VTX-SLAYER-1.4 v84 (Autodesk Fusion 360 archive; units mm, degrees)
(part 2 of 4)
sketch "Skizze49" plane through (0, 0, 7) normal (0, 0, 1) x axis (-1, 0, 0)
  curve K1 (-34.4729, 47.5027) -> (-34.8613, 50.4161)
  line L1 (-32.7992, 19.5622) -> (-34.4732, 21.3854)
  line L2 (21.7601, 20.324) -> (21.0607, 19.5622)
  curve K2 (14.991, 38.4401) -> (21.2218, 28.4813)
  curve K3 (14.991, 41.5582) -> (21.2218, 51.5169)
  line L3 (21.0607, 60.4361) -> (21.7601, 59.6743)
  line L4 (-34.4732, 58.6128) -> (-32.7992, 60.4361)
  line L5 (-23.7522, 44.4991) -> (-30.319, 44.4991)
  line L6 (-30.319, 41.4991) -> (-23.7522, 41.4991)
  line L7 (-23.7522, 38.4991) -> (-30.319, 38.4991)
  line L8 (-30.319, 35.4991) -> (-23.7522, 35.4991)
  curve K4 (-21.4163, 20.9358) -> (-22.7131, 20.0338)
  curve K5 (-21.4163, 59.0625) -> (-22.7131, 59.9644)
  curve K6 (23.3399, 24.4614) -> (21.2218, 28.4813)
  curve K7 (21.2218, 51.5169) -> (23.3399, 55.5369)
  line L9 (-26.3392, 32.4991) -> (-30.319, 32.4991)
  line L10 (-30.319, 29.4991) -> (-26.3392, 29.4991)
  curve K8 (-34.4732, 21.3854) -> (-34.8613, 29.5821)
  curve K9 (-34.8613, 50.4161) -> (-34.4732, 58.6128)
  curve K10 (-34.2161, 44.4991) -> (-34.4729, 47.5027)
  curve K11 (-34.0692, 39.9991) -> (-34.0919, 41.4991)
  curve K12 (-34.0919, 38.4991) -> (-34.0692, 39.9991)
  curve K13 (-34.0919, 38.4991) -> (-34.2161, 35.4991)
  curve K14 (-34.4729, 32.4955) -> (-34.2161, 35.4991)
  line L11 (-26.3392, 50.4991) -> (-30.319, 50.4991)
  line L12 (-30.319, 47.4991) -> (-26.3392, 47.4991)
  curve K15 (-5.8693, 25.0204) -> (1.6863, 24.3869)
  curve K16 (-5.8693, 54.9778) -> (1.6863, 55.6114)
  curve K17 (-32.7992, 19.5622) -> (-25.5215, 18.3445)
  curve K18 (-22.7131, 20.0338) -> (-25.5215, 18.3445)
  curve K19 (-5.8693, 25.0204) -> (-13.4249, 24.3869)
  curve K20 (10.9746, 20.0338) -> (13.7829, 18.3445)
  curve K21 (13.7829, 18.3445) -> (21.0607, 19.5622)
  curve K22 (14.9178, 39.9991) -> (14.991, 38.4401)
  curve K23 (14.9178, 39.9991) -> (14.991, 41.5582)
  curve K24 (13.7829, 61.6537) -> (21.0607, 60.4361)
  curve K25 (10.9746, 59.9644) -> (13.7829, 61.6537)
  curve K26 (-5.8693, 54.9778) -> (-13.4249, 55.6114)
  curve K27 (-22.7131, 59.9644) -> (-25.5215, 61.6537)
  curve K28 (-32.7992, 60.4361) -> (-25.5215, 61.6537)
  curve K29 (-34.0919, 41.4991) -> (-34.2161, 44.4991)
  curve K30 (-21.2077, 21.0728) -> (-21.4163, 20.9358)
  curve K31 (-13.5094, 24.37) -> (-21.2077, 21.0728)
  curve K32 (-13.4249, 24.3869) -> (-13.5094, 24.37)
  curve K33 (1.6863, 24.3869) -> (1.7709, 24.37)
  curve K34 (9.4692, 21.0728) -> (1.7709, 24.37)
  curve K35 (9.4692, 21.0728) -> (9.6778, 20.9358)
  curve K36 (9.6778, 20.9358) -> (10.9746, 20.0338)
  curve K37 (9.6778, 59.0625) -> (10.9746, 59.9644)
  curve K38 (9.4692, 58.9255) -> (9.6778, 59.0625)
  curve K39 (1.7709, 55.6283) -> (9.4692, 58.9255)
  curve K40 (1.6863, 55.6114) -> (1.7709, 55.6283)
  curve K41 (-13.4249, 55.6114) -> (-13.5094, 55.6283)
  curve K42 (-21.2077, 58.9255) -> (-13.5094, 55.6283)
  curve K43 (-21.2077, 58.9255) -> (-21.4163, 59.0625)
  curve K44 (-34.4729, 32.4955) -> (-34.8613, 29.5821)
  circle C1 centre (4.1749, 29.9966) radius 1.05
  circle C2 centre (-15.8251, 49.9966) radius 1.05
  circle C3 centre (-15.8251, 29.9966) radius 1.05
  circle C4 centre (4.1749, 49.9966) radius 1.05
  circle C5 centre (18.1718, 23.4983) radius 2
  circle C6 centre (-29.8282, 23.4983) radius 2
  circle C7 centre (18.1718, 56.4983) radius 2
  circle C8 centre (-29.8282, 56.4983) radius 2
  circle C9 centre (-15.8251, 49.9966) radius 2.1
  circle C10 centre (-15.8251, 29.9966) radius 2.1
  circle C11 centre (4.1749, 29.9966) radius 2.1
  circle C12 centre (4.1749, 49.9966) radius 2.1
  circle C13 centre (-5.8313, 39.9999) radius 2.625
  circle C14 centre (-15.8251, 49.9966) radius 1.05
  circle C15 centre (-15.8251, 29.9966) radius 1.05
  circle C16 centre (4.1749, 49.9966) radius 1.05
  circle C17 centre (4.1749, 29.9966) radius 1.05
  circle C18 centre (-15.8282, 29.9983) radius 2.1
  circle C19 centre (-15.8282, 49.9983) radius 2.1
  circle C20 centre (4.1718, 29.9983) radius 2.1
  circle C21 centre (-5.8282, 39.9983) radius 3
  circle C22 centre (4.1718, 49.9983) radius 2.1
  arc A1 centre (-23.7522, 42.9991) radius 1.5 clockwise from (-23.7522, 44.4991) to (-23.7522, 41.4991)
  arc A2 centre (-30.319, 42.9991) radius 1.5 clockwise from (-30.319, 41.4991) to (-30.319, 44.4991)
  arc A3 centre (-30.319, 36.9991) radius 1.5 clockwise from (-30.319, 35.4991) to (-30.319, 38.4991)
  arc A4 centre (-23.7522, 36.9991) radius 1.5 clockwise from (-23.7522, 38.4991) to (-23.7522, 35.4991)
  arc A5 centre (17.3404, 24.3819) radius 6 clockwise from (23.3399, 24.4614) to (21.7601, 20.324)
  arc A6 centre (17.3404, 55.6164) radius 6 clockwise from (21.7601, 59.6743) to (23.3399, 55.5369)
  arc A7 centre (-26.3392, 30.9991) radius 1.5 clockwise from (-26.3392, 32.4991) to (-26.3392, 29.4991)
  arc A8 centre (-30.319, 30.9991) radius 1.5 clockwise from (-30.319, 29.4991) to (-30.319, 32.4991)
  arc A9 centre (-30.319, 48.9991) radius 1.5 clockwise from (-30.319, 47.4991) to (-30.319, 50.4991)
  arc A10 centre (-26.3392, 48.9991) radius 1.5 clockwise from (-26.3392, 50.4991) to (-26.3392, 47.4991)
  circle C23 centre (-29.8693, 56.4991) radius 2.55
  circle C24 centre (18.1307, 56.4991) radius 2.55
  circle C25 centre (-29.8693, 23.4991) radius 2.55
  circle C26 centre (18.1307, 23.4991) radius 2.55
  circle C27 centre (-5.8693, 39.9991) radius 2.55
  circle C28 centre (-15.8693, 49.9991) radius 1.05
  circle C29 centre (4.1307, 49.9991) radius 1.05
  circle C30 centre (-15.8693, 29.9991) radius 1.05
  circle C31 centre (4.1307, 29.9991) radius 1.05
  dimension "d443" diameter C5 = 4
  dimension "d444" diameter C6 = 4 (= "d443")
  dimension "d445" diameter C7 = 4 (= "d443")
  dimension "d446" diameter C8 = 4 (= "d443")
work_plane "WorkPlane5" AlongDistance 25
sketch "Skizze50" plane through (0, 0, 32) normal (0, 0, 1) x axis (-1, 0, 0)
  line L1 (-34.2161, 35.4991) -> (-33.5931, 35.4991)
  line L2 (-34.2172, 44.4991) -> (-33.5931, 44.4991)
  line L3 (-26.4943, 39.9991) -> (14.9178, 39.9991)
  line L4 (34.1307, 43.8641) -> (34.1307, 36.1341)
  line L5 (21.0607, 19.5622) -> (32.5504, 32.0762)
  line L6 (-32.7992, 19.5622) -> (-33.4986, 20.324)
  line L7 (32.5504, 32.0762) -> (21.0607, 19.5622)
  line L8 (34.1307, 43.8641) -> (34.1307, 36.1341)
  line L9 (21.0607, 60.4361) -> (32.5504, 47.922)
  line L10 (-33.4986, 59.6743) -> (-32.7992, 60.4361)
  curve K1 (-34.4729, 47.5027) -> (-34.8613, 50.4161)
  line L11 (-32.7992, 19.5622) -> (-34.4732, 21.3854)
  line L12 (21.7601, 20.324) -> (21.0607, 19.5622)
  line L13 (21.0607, 60.4361) -> (21.7601, 59.6743)
  line L14 (-34.4732, 58.6128) -> (-32.7992, 60.4361)
  curve K2 (9.6778, 20.9358) -> (10.9746, 20.0338)
  curve K3 (9.6778, 59.0625) -> (10.9746, 59.9644)
  curve K4 (-21.4163, 20.9358) -> (-22.7131, 20.0338)
  curve K5 (-21.4163, 59.0625) -> (-22.7131, 59.9644)
  curve K6 (-35.0785, 55.5369) -> (-32.9603, 51.5169)
  curve K7 (-32.9603, 28.4813) -> (-35.0785, 24.4614)
  curve K8 (23.3399, 24.4614) -> (21.2218, 28.4813)
  curve K9 (21.2218, 51.5169) -> (23.3399, 55.5369)
  line L15 (-26.3392, 32.4991) -> (-30.319, 32.4991)
  line L16 (-30.319, 29.4991) -> (-26.3392, 29.4991)
  curve K10 (-34.4732, 21.3854) -> (-34.8613, 29.5821)
  curve K11 (-34.8613, 50.4161) -> (-34.4732, 58.6128)
  curve K12 (-34.2161, 44.4991) -> (-34.4729, 47.5027)
  curve K13 (-34.0919, 41.4991) -> (-34.2161, 44.4991)
  curve K14 (-34.0692, 39.9991) -> (-34.0919, 41.4991)
  curve K15 (-34.0919, 38.4991) -> (-34.0692, 39.9991)
  curve K16 (-34.0919, 38.4991) -> (-34.2161, 35.4991)
  curve K17 (-34.4729, 32.4955) -> (-34.2161, 35.4991)
  line L17 (-26.3392, 50.4991) -> (-30.319, 50.4991)
  line L18 (-30.319, 47.4991) -> (-26.3392, 47.4991)
  curve K18 (-5.8693, 54.9778) -> (1.6863, 55.6114)
  curve K19 (-5.8693, 54.9778) -> (-13.4249, 55.6114)
  curve K20 (-5.8693, 25.0204) -> (-13.4249, 24.3869)
  curve K21 (-5.8693, 25.0204) -> (1.6863, 24.3869)
  curve K22 (-5.8693, 25.0204) -> (1.6863, 24.3869)
  curve K23 (-5.8693, 54.9778) -> (1.6863, 55.6114)
  curve K24 (-25.5215, 18.3445) -> (-32.7992, 19.5622)
  curve K25 (-22.7131, 20.0338) -> (-25.5215, 18.3445)
  curve K26 (10.9746, 20.0338) -> (13.7829, 18.3445)
  curve K27 (21.0607, 19.5622) -> (13.7829, 18.3445)
  curve K28 (21.0607, 60.4361) -> (13.7829, 61.6537)
  curve K29 (10.9746, 59.9644) -> (13.7829, 61.6537)
  curve K30 (-22.7131, 59.9644) -> (-25.5215, 61.6537)
  curve K31 (-25.5215, 61.6537) -> (-32.7992, 60.4361)
  curve K32 (-32.7992, 19.5622) -> (-25.5215, 18.3445)
  curve K33 (-22.7131, 20.0338) -> (-25.5215, 18.3445)
  curve K34 (-5.8693, 25.0204) -> (-13.4249, 24.3869)
  curve K35 (10.9746, 20.0338) -> (13.7829, 18.3445)
  curve K36 (13.7829, 18.3445) -> (21.0607, 19.5622)
  curve K37 (13.7829, 61.6537) -> (21.0607, 60.4361)
  curve K38 (10.9746, 59.9644) -> (13.7829, 61.6537)
  curve K39 (-5.8693, 54.9778) -> (-13.4249, 55.6114)
  curve K40 (-22.7131, 59.9644) -> (-25.5215, 61.6537)
  curve K41 (-32.7992, 60.4361) -> (-25.5215, 61.6537)
  curve K42 (-21.4163, 20.9358) -> (-22.7131, 20.0338)
  curve K43 (-13.5094, 24.37) -> (-21.4163, 20.9358)
  curve K44 (-13.4249, 24.3869) -> (-13.5094, 24.37)
  curve K45 (1.6863, 24.3869) -> (1.7709, 24.37)
  curve K46 (1.7709, 24.37) -> (9.6778, 20.9358)
  curve K47 (1.7709, 55.6283) -> (9.6778, 59.0625)
  curve K48 (1.6863, 55.6114) -> (1.7709, 55.6283)
  curve K49 (-13.4249, 55.6114) -> (-13.5094, 55.6283)
  curve K50 (-13.5094, 55.6283) -> (-21.4163, 59.0625)
  curve K51 (-21.4163, 59.0625) -> (-22.7131, 59.9644)
  curve K52 (-21.2077, 21.0728) -> (-21.4163, 20.9358)
  curve K53 (-13.5094, 24.37) -> (-21.2077, 21.0728)
  curve K54 (-13.4249, 24.3869) -> (-13.5094, 24.37)
  curve K55 (1.6863, 24.3869) -> (1.7709, 24.37)
  curve K56 (9.4692, 21.0728) -> (1.7709, 24.37)
  curve K57 (9.4692, 21.0728) -> (9.6778, 20.9358)
  curve K58 (9.6778, 20.9358) -> (10.9746, 20.0338)
  curve K59 (9.6778, 59.0625) -> (10.9746, 59.9644)
  curve K60 (9.4692, 58.9255) -> (9.6778, 59.0625)
  curve K61 (1.7709, 55.6283) -> (9.4692, 58.9255)
  curve K62 (1.6863, 55.6114) -> (1.7709, 55.6283)
  curve K63 (-13.4249, 55.6114) -> (-13.5094, 55.6283)
  curve K64 (-21.2077, 58.9255) -> (-13.5094, 55.6283)
  curve K65 (-21.2077, 58.9255) -> (-21.4163, 59.0625)
  curve K66 (-34.4729, 32.4955) -> (-34.8613, 29.5821)
  line L19 (3.2014, 37.2064) -> (18.1307, 23.4991)
  line L20 (3.2014, 42.7918) -> (18.1307, 56.4991)
  line L21 (25.9, 31.9611) -> (18.1307, 23.4991)
  line L22 (25.9, 48.0372) -> (18.1307, 56.4991)
  line L23 (6.5519, 27.8311) -> (12.5889, 23.7993)
  line L24 (6.5519, 52.1671) -> (12.5889, 56.1989)
  line L25 (-12.7701, 29.0204) -> (1.0316, 29.0204)
  line L26 (-12.7701, 50.9778) -> (1.0316, 50.9778)
  line L27 (19.9777, 28.7328) -> (21.5825, 30.4807)
  line L28 (19.9777, 51.2654) -> (21.5825, 49.5175)
  line L29 (-26.1937, 36.9643) -> (-19.1192, 29.9733)
  line L30 (-26.1937, 39.9991) -> (-26.1937, 36.9643)
  line L31 (-26.1937, 43.034) -> (-19.1192, 50.025)
  line L32 (-26.1937, 39.9991) -> (-26.1937, 43.034)
  line L33 (39.4861, -5.3562) -> (4.1307, 29.9991)
  line L34 (54.1307, 29.9991) -> (4.1307, 29.9991)
  line L35 (-51.2246, -5.3562) -> (-15.8693, 29.9991)
  line L36 (34.1307, 29.9991) -> (-15.8693, 29.9991)
  line L37 (-5.7883, 39.9991) -> (4.1307, 29.9991)
  line L38 (-5.7883, 39.9991) -> (-15.8693, 29.9991)
  line L39 (39.4861, 85.3545) -> (4.1307, 49.9991)
  line L40 (-5.7883, 39.9991) -> (4.1307, 49.9991)
  line L41 (-5.7883, 39.9991) -> (-15.8693, 49.9991)
  line L42 (-51.2246, 85.3545) -> (-15.8693, 49.9991)
  line L43 (-2.5295, 39.9991) -> (4.166, 33.2489)
  line L44 (0.9769, 30.784) -> (-5.7883, 37.6045)
  line L45 (-13.4558, 29.9991) -> (-5.7883, 37.6045)
  line L46 (-15.8592, 33.2491) -> (-9.0541, 39.9991)
  line L47 (0.9769, 49.2142) -> (-5.7883, 42.3937)
  line L48 (-2.5295, 39.9991) -> (4.166, 46.7493)
  line L49 (-13.4558, 49.9991) -> (-5.7883, 42.3937)
  line L50 (-15.8592, 46.7491) -> (-9.0541, 39.9991)
  line L51 (14.9457, 39.9991) -> (6.7725, 31.8921)
  line L52 (7.6315, 27.1101) -> (18.0788, 37.4728)
  line L53 (7.6315, 52.8881) -> (18.0788, 42.5254)
  line L54 (14.9457, 39.9991) -> (6.7725, 48.1061)
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  point P2 (-33.5931, 39.9991)
  point P7 (-26.4943, 39.9991)
  point P94 (-34.2161, 35.4991)
  point P141 (-34.2161, 35.4991)
  point P56 (18.1307, 23.4991)
  point P142 (18.1307, 23.4991)
  point P144 (18.1307, 56.4991)
  point P143 (3.2014, 37.2064)
  point P145 (3.2014, 42.7918)
  point P147 (18.1307, 56.4991)
  point P146 (25.9, 31.9611)
  point P148 (25.9, 48.0372)
  point P6 (14.9178, 39.9991)
  point P39 (31.849, 39.9991)
  point P150 (18.1307, 23.4991)
  point P156 (12.5889, 23.7993)
  point P158 (12.5889, 56.1989)
  point P157 (6.5519, 27.8311)
  point P159 (6.5519, 52.1671)
  point P160 (1.0316, 29.0204)
  point P162 (1.0316, 50.9778)
  point P161 (-12.7701, 29.0204)
  point P163 (-12.7701, 50.9778)
  point P164 (21.5825, 30.4807)
  point P166 (21.5825, 49.5175)
  point P165 (19.9777, 28.7328)
  point P167 (19.9777, 51.2654)
  point P170 (-26.1937, 39.9991)
  point P168 (-19.1192, 29.9733)
  point P171 (-19.1192, 50.025)
  point P169 (-26.1937, 36.9643)
  point P172 (-26.1937, 43.034)
  point P173 (-26.1937, 39.9991)
  point P106 (4.1307, 29.9991)
  point P174 (4.1307, 29.9991)
  point P72 (-15.8693, 29.9991)
  point P177 (-15.8693, 29.9991)
  point P180 (-5.7883, 39.9991)
  point P181 (-15.8693, 29.9991)
  point P182 (4.1307, 49.9991)
  point P175 (39.4861, -5.3562)
  point P183 (39.4861, 85.3545)
  point P186 (-15.8693, 49.9991)
  point P178 (-51.2246, -5.3562)
  point P187 (-51.2246, 85.3545)
  point P184 (-5.7883, 39.9991)
  point P185 (-15.8693, 49.9991)
  point P189 (-2.5295, 39.9991)
  point P190 (-5.7883, 37.6045)
  point P192 (-13.4558, 29.9991)
  point P193 (-9.0541, 39.9991)
  point P188 (4.166, 33.2489)
  point P197 (4.166, 46.7493)
  point P198 (-2.5295, 39.9991)
  point P195 (-5.7883, 42.3937)
  point P191 (0.9769, 30.784)
  point P196 (0.9769, 49.2142)
  point P199 (-13.4558, 49.9991)
  point P200 (-9.0541, 39.9991)
  point P194 (-15.8592, 33.2491)
  point P201 (-15.8592, 46.7491)
  point P203 (14.9457, 39.9991)
  point P205 (7.6315, 27.1101)
  point P202 (6.7725, 31.8921)
  point P208 (6.7725, 48.1061)
  point P209 (14.9457, 39.9991)
  point P204 (18.0788, 37.4728)
  point P206 (18.0788, 42.5254)
  point P207 (7.6315, 52.8881)
  point P128 (9.4692, 21.0728)
  point P74 (-5.8693, 25.0204)
  horizontal L1
  horizontal L2
  horizontal P2 P7
  coincident P94 P141
  coincident P56 P142
  symmetric L3 P142 P144
  symmetric L3 P143 P145
  perpendicular L19 L21
  parallel L5 L21
  symmetric L3 P142 P147
  symmetric L3 P146 P148
  horizontal P6 P39
  coincident P142 P150
  symmetric L3 P156 P158
  symmetric L3 P157 P159
  horizontal L25
  symmetric L3 P160 P162
  symmetric L3 P161 P163
  parallel L21 L27
  symmetric L3 P164 P166
  symmetric L3 P165 P167
  coincident L3 P170
  perpendicular L3 L30
  symmetric L3 P168 P171
  symmetric L3 P169 P172
  symmetric L3 P170 P173
  horizontal L34
  coincident P106 P174
  horizontal L36
  coincident P72 P177
  midpoint L3 P180
  coincident P72 P181
  symmetric L3 P174 P182
  symmetric L3 P175 P183
  symmetric L3 P177 P186
  symmetric L3 P178 P187
  symmetric L3 P180 P184
  symmetric L3 P181 P185
  coincident L3 P189
  parallel L37 L43
  parallel L37 L44
  vertical P180 P190
  coincident L36 P192
  perpendicular L44 L45
  coincident L3 P193
  parallel L45 L46
  symmetric L3 P188 P197
  symmetric L3 P189 P198
  symmetric L3 P190 P195
  symmetric L3 P191 P196
  symmetric L3 P192 P199
  symmetric L3 P193 P200
  symmetric L3 P194 P201
  coincident L3 P203
  coincident L23 P205
  parallel L51 L52
  perpendicular L37 L51
  symmetric L3 P202 P208
  symmetric L3 P203 P209
  symmetric L3 P204 P206
  symmetric L3 P205 P207
  dimension "d586" diameter = 9
  dimension "d636" diameter = 20
  dimension "d1095" distance = 4
  dimension "d1096" distance = 4
  dimension "d1098" distance = 2.2
  dimension "d1100" distance = 2.2
  dimension "d1101" distance P128 L23 = 4
  dimension "d1103" distance P74 L25 = 4
  dimension "d1104" distance L5 L27 = 7
  dimension "d1105" angle L33 L34 = 45
  dimension "d1106" distance P174 P175 = 50
  dimension "d1107" angle L35 L36 = 135 (= "90 deg + 45 deg")
  dimension "d1108" distance P177 P178 = 50
  dimension "d1111" distance L43 L44 = 4
  dimension "d1112" distance L45 L46 = 4 (= "d1111")
  dimension "d1113" distance L51 L52 = 4
extrude "Extrude78" new body sketch "Skizze50" along normal blind 1.5
fillet "Fillet34" radius 4
fillet "Fillet103" radius 4
fillet "Fillet37" radius 3
fillet "Fillet104" radius 4
fillet "Fillet105" radius 3
fillet "Fillet106" radius 2
fillet "Fillet107" radius 5
sketch "weight-reduction-m-top" plane through (0, 0, 7) normal (0, 0, 1) x axis (-1, 0, 0)
  line L1 (-26.3392, 32.4991) -> (-30.319, 32.4991)
  line L2 (-30.319, 29.4991) -> (-26.3392, 29.4991)
  curve K1 (-34.4729, 32.4955) -> (-34.8613, 29.5821)
  curve K2 (-34.4732, 21.3854) -> (-34.8613, 29.5821)
  line L3 (-32.7992, 19.5622) -> (-34.4732, 21.3854)
  curve K3 (-21.4163, 20.9358) -> (-22.7131, 20.0338)
  line L4 (21.7601, 20.324) -> (21.0607, 19.5622)
  curve K4 (23.3399, 24.4614) -> (21.2218, 28.4813)
  curve K5 (14.991, 38.4401) -> (21.2218, 28.4813)
  curve K6 (14.991, 41.5582) -> (21.2218, 51.5169)
  curve K7 (21.2218, 51.5169) -> (23.3399, 55.5369)
  line L5 (21.0607, 60.4361) -> (21.7601, 59.6743)
  curve K8 (-21.4163, 59.0625) -> (-22.7131, 59.9644)
  line L6 (-34.4732, 58.6128) -> (-32.7992, 60.4361)
  curve K9 (-34.8613, 50.4161) -> (-34.4732, 58.6128)
  curve K10 (-34.4729, 47.5027) -> (-34.8613, 50.4161)
  curve K11 (-34.2161, 44.4991) -> (-34.4729, 47.5027)
  curve K12 (-34.0919, 41.4991) -> (-34.2161, 44.4991)
  curve K13 (-34.0692, 39.9991) -> (-34.0919, 41.4991)
  curve K14 (-34.0919, 38.4991) -> (-34.0692, 39.9991)
  curve K15 (-34.0919, 38.4991) -> (-34.2161, 35.4991)
  curve K16 (-34.4729, 32.4955) -> (-34.2161, 35.4991)
  line L7 (-23.7522, 38.4991) -> (-30.319, 38.4991)
  line L8 (-30.319, 35.4991) -> (-23.7522, 35.4991)
  line L9 (-23.7522, 44.4991) -> (-30.319, 44.4991)
  line L10 (-30.319, 41.4991) -> (-23.7522, 41.4991)
  line L11 (-26.3392, 50.4991) -> (-30.319, 50.4991)
  line L12 (-30.319, 47.4991) -> (-26.3392, 47.4991)
  line L13 (-3, 17) -> (8, 17)
  line L14 (38, 44) -> (38, 33)
  line L15 (-2.454, 39.9991) -> (16.5436, 39.9991)
  line L16 (-5.8693, 35.997) -> (-5.8693, 24.0226)
  curve K17 (11.053, 39.9991) -> (5.0002, 32.3431)
  curve K18 (11.053, 41.4602) -> (11.053, 38.538)
  curve K19 (5.9236, 32.0012) -> (4.0767, 32.6849)
  curve K20 (11.053, 39.9991) -> (5.0002, 47.6552)
  curve K21 (5.9236, 47.997) -> (4.0767, 47.3133)
  curve K22 (11.053, 38.538) -> (11.053, 41.4602)
  curve K23 (-15.8119, 47.4998) -> (-15.9266, 32.4985)
  curve K24 (-16.9524, 32.4749) -> (-14.9008, 32.522)
  curve K25 (-14.7861, 47.5233) -> (-16.8377, 47.4762)
  curve K26 (-5.8693, 30.0098) -> (2.0117, 31.3257)
  curve K27 (1.7635, 30.9291) -> (2.26, 31.7222)
  curve K28 (-7, 30.0098) -> (-4.7385, 30.0098)
  curve K29 (-5.8693, 30.0098) -> (-13.7502, 31.3257)
  curve K30 (-13.502, 30.9291) -> (-13.9985, 31.7222)
  curve K31 (-4.7385, 30.0098) -> (-7, 30.0098)
  curve K32 (-5.8693, 49.9885) -> (-13.7502, 48.6726)
  curve K33 (-13.502, 49.0691) -> (-13.9985, 48.276)
  curve K34 (-4.7385, 49.9885) -> (-7, 49.9885)
  curve K35 (-5.8693, 49.9885) -> (2.0117, 48.6726)
  curve K36 (1.7635, 49.0691) -> (2.26, 48.276)
  curve K37 (-7, 49.9885) -> (-4.7385, 49.9885)
  curve K38 (-5.8693, 25.0204) -> (1.6863, 24.3869)
  curve K39 (-5.8693, 54.9778) -> (1.6863, 55.6114)
  curve K40 (-32.7992, 19.5622) -> (-25.5215, 18.3445)
  curve K41 (-22.7131, 20.0338) -> (-25.5215, 18.3445)
  curve K42 (-5.8693, 25.0204) -> (-13.4249, 24.3869)
  curve K43 (10.9746, 20.0338) -> (13.7829, 18.3445)
  curve K44 (13.7829, 18.3445) -> (21.0607, 19.5622)
  curve K45 (14.9178, 39.9991) -> (14.991, 38.4401)
  curve K46 (14.9178, 39.9991) -> (14.991, 41.5582)
  curve K47 (13.7829, 61.6537) -> (21.0607, 60.4361)
  curve K48 (10.9746, 59.9644) -> (13.7829, 61.6537)
  curve K49 (-5.8693, 54.9778) -> (-13.4249, 55.6114)
  curve K50 (-22.7131, 59.9644) -> (-25.5215, 61.6537)
  curve K51 (-32.7992, 60.4361) -> (-25.5215, 61.6537)
  curve K52 (-21.2077, 21.0728) -> (-21.4163, 20.9358)
  curve K53 (-13.5094, 24.37) -> (-21.2077, 21.0728)
  curve K54 (-13.4249, 24.3869) -> (-13.5094, 24.37)
  curve K55 (1.6863, 24.3869) -> (1.7709, 24.37)
  curve K56 (9.4692, 21.0728) -> (1.7709, 24.37)
  curve K57 (9.4692, 21.0728) -> (9.6778, 20.9358)
  curve K58 (9.6778, 20.9358) -> (10.9746, 20.0338)
  curve K59 (9.6778, 59.0625) -> (10.9746, 59.9644)
  curve K60 (9.4692, 58.9255) -> (9.6778, 59.0625)
  curve K61 (1.7709, 55.6283) -> (9.4692, 58.9255)
  curve K62 (1.6863, 55.6114) -> (1.7709, 55.6283)
  curve K63 (-13.4249, 55.6114) -> (-13.5094, 55.6283)
  curve K64 (-21.2077, 58.9255) -> (-13.5094, 55.6283)
  curve K65 (-21.2077, 58.9255) -> (-21.4163, 59.0625)
  arc A1 centre (-26.3392, 30.9991) radius 1.5 clockwise from (-26.3392, 32.4991) to (-26.3392, 29.4991)
  arc A2 centre (-30.319, 30.9991) radius 1.5 clockwise from (-30.319, 29.4991) to (-30.319, 32.4991)
  arc A3 centre (17.3404, 24.3819) radius 6 clockwise from (23.3399, 24.4614) to (21.7601, 20.324)
  arc A4 centre (17.3404, 55.6164) radius 6 clockwise from (21.7601, 59.6743) to (23.3399, 55.5369)
  arc A5 centre (-23.7522, 36.9991) radius 1.5 clockwise from (-23.7522, 38.4991) to (-23.7522, 35.4991)
  arc A6 centre (-30.319, 36.9991) radius 1.5 clockwise from (-30.319, 35.4991) to (-30.319, 38.4991)
  arc A7 centre (-30.319, 42.9991) radius 1.5 clockwise from (-30.319, 41.4991) to (-30.319, 44.4991)
  arc A8 centre (-23.7522, 42.9991) radius 1.5 clockwise from (-23.7522, 44.4991) to (-23.7522, 41.4991)
  arc A9 centre (-30.319, 48.9991) radius 1.5 clockwise from (-30.319, 47.4991) to (-30.319, 50.4991)
  arc A10 centre (-26.3392, 48.9991) radius 1.5 clockwise from (-26.3392, 50.4991) to (-26.3392, 47.4991)
  circle C1 centre (-29.8693, 56.4991) radius 2.55
  circle C2 centre (18.1307, 56.4991) radius 2.55
  circle C3 centre (-29.8693, 23.4991) radius 2.55
  circle C4 centre (18.1307, 23.4991) radius 2.55
  circle C5 centre (4.1307, 29.9991) radius 2.5
  circle C6 centre (-15.8693, 29.9991) radius 2.5
  circle C7 centre (4.1307, 49.9991) radius 2.5
  circle C8 centre (-15.8693, 49.9991) radius 2.5
  circle C9 centre (-5.8693, 39.9991) radius 2.55
  circle C10 centre (-15.8693, 49.9991) radius 1.05
  circle C11 centre (4.1307, 49.9991) radius 1.05
  circle C12 centre (-15.8693, 29.9991) radius 1.05
  circle C13 centre (4.1307, 29.9991) radius 1.05
  point P70 (11.053, 39.9991)
  point P73 (5.0002, 32.3431)
  point P77 (11.053, 39.9991)
  point P71 (11.053, 38.538)
  point P80 (11.053, 41.4602)
  point P72 (11.053, 41.4602)
  point P81 (11.053, 38.538)
  point P76 (5.0002, 47.6552)
  point P74 (4.0767, 32.6849)
  point P78 (4.0767, 47.3133)
  point P75 (5.9236, 32.0012)
  point P79 (5.9236, 47.997)
  point P82 (-15.9266, 32.4985)
  point P83 (-15.8119, 47.4998)
  point P88 (2.0117, 31.3257)
  point P89 (-5.8693, 30.0098)
  point P94 (-13.7502, 31.3257)
  point P95 (-5.8693, 30.0098)
  point P90 (2.26, 31.7222)
  point P96 (-13.9985, 31.7222)
  point P91 (1.7635, 30.9291)
  point P97 (-13.502, 30.9291)
  point P92 (-4.7385, 30.0098)
  point P98 (-7, 30.0098)
  point P93 (-7, 30.0098)
  point P99 (-4.7385, 30.0098)
  point P106 (2.0117, 48.6726)
  point P107 (-5.8693, 49.9885)
  point P108 (2.26, 48.276)
  point P109 (1.7635, 49.0691)
  point P110 (-4.7385, 49.9885)
  point P111 (-7, 49.9885)
  point P100 (-13.7502, 48.6726)
  point P101 (-5.8693, 49.9885)
  point P102 (-13.9985, 48.276)
  point P103 (-13.502, 49.0691)
  point P104 (-7, 49.9885)
  point P105 (-4.7385, 49.9885)
  horizontal L13
  perpendicular L13 L14
  coincident L15 P70
  midpoint P70 K18
  coincident C5 P73
  midpoint P73 K19
  tangent C5 K19
  parallel L14 K18
  symmetric L15 P70 P77
  symmetric L15 P71 P80
  symmetric L15 P72 P81
  symmetric L15 P73 P76
  symmetric L15 P74 P78
  symmetric L15 P75 P79
  coincident C6 P82
  coincident C8 P83
  midpoint P82 K24
  tangent C6 K24
  midpoint P83 K25
  tangent C8 K25
  parallel K24 K25
  equal K24 K25
  coincident C5 P88
  midpoint L16 P89
  midpoint P88 K27
  tangent C5 K27
  midpoint P89 K28
  parallel L15 K28
  symmetric L16 P88 P94
  symmetric L16 P89 P95
  symmetric L16 P90 P96
  symmetric L16 P91 P97
  symmetric L16 P92 P98
  symmetric L16 P93 P99
  symmetric L15 P88 P106
  symmetric L15 P89 P107
  symmetric L15 P90 P108
  symmetric L15 P91 P109
  symmetric L15 P92 P110
  symmetric L15 P93 P111
  symmetric L15 P94 P100
  symmetric L15 P95 P101
  symmetric L15 P96 P102
  symmetric L15 P97 P103
  symmetric L15 P98 P104
  symmetric L15 P99 P105
  dimension "d692" diameter C5 = 5
  dimension "d693" diameter C6 = 5
  dimension "d694" diameter C7 = 5
  dimension "d695" diameter C8 = 5
extrude "Extrude85" cut sketch "weight-reduction-m-top" profile of C5 C6 C7 C8 K17 K20 K23 K26 K29 K32 K35 against normal blind 2
sketch "weight-reduction-m-center" plane through (0, 0, 5) normal (0, 0, 1) x axis (-1, 0, 0)
  curve K1 (-26.6974, 39.9991) -> (-25.0329, 29.8104)
  curve K2 (-24.8323, 29.8846) -> (-25.0329, 29.8104)
  curve K3 (-22.3693, 34.4991) -> (-24.8323, 29.8846)
  line L1 (-19.3693, 25.3947) -> (-19.3693, 34.4991)
  curve K4 (-17.2278, 23.275) -> (-19.3693, 25.3947)
  curve K5 (5.4893, 23.275) -> (7.6307, 25.3947)
  line L2 (7.6307, 34.4991) -> (7.6307, 25.3947)
  curve K6 (10.6307, 34.4991) -> (13.0937, 29.8846)
  curve K7 (13.0937, 29.8846) -> (13.2943, 29.8104)
  curve K8 (14.9589, 39.9991) -> (13.2943, 29.8104)
  curve K9 (14.9589, 39.9991) -> (13.2943, 50.1878)
  curve K10 (13.0937, 50.1137) -> (13.2943, 50.1878)
  curve K11 (10.6307, 45.4991) -> (13.0937, 50.1137)
  line L3 (7.6307, 54.6035) -> (7.6307, 45.4991)
  curve K12 (5.4893, 56.7233) -> (7.6307, 54.6035)
  curve K13 (-17.2278, 56.7233) -> (-19.3693, 54.6035)
  line L4 (-19.3693, 45.4991) -> (-19.3693, 54.6035)
  curve K14 (-22.3693, 45.4991) -> (-24.8323, 50.1137)
  curve K15 (-24.8323, 50.1137) -> (-25.0329, 50.1878)
  curve K16 (-26.6974, 39.9991) -> (-25.0329, 50.1878)
  curve K17 (-5.8693, 25.0204) -> (-17.2278, 23.275)
  curve K18 (-5.8693, 25.0204) -> (5.4893, 23.275)
  curve K19 (-5.8693, 54.9778) -> (5.4893, 56.7233)
  curve K20 (-5.8693, 54.9778) -> (-17.2278, 56.7233)
  arc A1 centre (-20.8693, 34.4991) radius 1.5 clockwise from (-22.3693, 34.4991) to (-19.3693, 34.4991)
  arc A2 centre (9.1307, 34.4991) radius 1.5 clockwise from (7.6307, 34.4991) to (10.6307, 34.4991)
  arc A3 centre (9.1307, 45.4991) radius 1.5 clockwise from (10.6307, 45.4991) to (7.6307, 45.4991)
  arc A4 centre (-20.8693, 45.4991) radius 1.5 clockwise from (-19.3693, 45.4991) to (-22.3693, 45.4991)
  circle C1 centre (4.1307, 49.9991) radius 2.1
  circle C2 centre (-15.8693, 49.9991) radius 2.1
  circle C3 centre (-15.8693, 29.9991) radius 2.1
  circle C4 centre (4.1307, 29.9991) radius 2.1
  circle C5 centre (-5.8693, 39.9991) radius 1.55
  circle C6 centre (-5.8693, 39.9991) radius 8.75
  circle C7 centre (4.1307, 29.9991) radius 1.05
  circle C8 centre (-15.8693, 29.9991) radius 1.05
  circle C9 centre (4.1307, 49.9991) radius 1.05
  circle C10 centre (-15.8693, 49.9991) radius 1.05
  concentric C5 C6
  concentric C4 C7
  concentric C3 C8
  concentric C1 C9
  concentric C2 C10
  dimension "d700" diameter C6 = 17.5
  dimension "d703" diameter C7 = 2.1
  dimension "d704" diameter C8 = 2.1 (= "d703")
  dimension "d705" diameter C9 = 2.1 (= "d703")
  dimension "d706" diameter C10 = 2.1 (= "d703")
extrude "Extrude86" cut sketch "weight-reduction-m-center" profile of C5 C6 against normal blind 2
extrude "Extrude87" add sketch "weight-reduction-m-center" profile of C1 C2 C3 C4 C7 C8 C9 C10 against normal blind 2
component_insert "Component Insert4"
sketch "cam-mount-base" plane through (0, 0, 7) normal (0, 0, 1) x axis (-1, 0, 0)
  curve K1 (2.0117, 48.6726) -> (-5.8693, 49.9885)
  curve K2 (11.053, 39.9991) -> (5.0002, 47.6552)
  curve K3 (5.0002, 32.3431) -> (11.053, 39.9991)
  curve K4 (-5.8693, 30.0098) -> (2.0117, 31.3257)
  curve K5 (-13.7502, 31.3257) -> (-5.8693, 30.0098)
  curve K6 (-15.8119, 47.4998) -> (-15.9266, 32.4985)
  curve K7 (-5.8693, 49.9885) -> (-13.7502, 48.6726)
  line L1 (-26.3392, 32.4991) -> (-30.319, 32.4991)
  line L2 (-30.319, 29.4991) -> (-26.3392, 29.4991)
  curve K8 (-34.4729, 32.4955) -> (-34.8613, 29.5821)
  curve K9 (-34.4732, 21.3854) -> (-34.8613, 29.5821)
  line L3 (-32.7992, 19.5622) -> (-34.4732, 21.3854)
  curve K10 (-21.4163, 20.9358) -> (-22.7131, 20.0338)
  line L4 (21.7601, 20.324) -> (21.0607, 19.5622)
  curve K11 (23.3399, 24.4614) -> (21.2218, 28.4813)
  curve K12 (14.991, 38.4401) -> (21.2218, 28.4813)
  curve K13 (14.991, 41.5582) -> (21.2218, 51.5169)
  curve K14 (21.2218, 51.5169) -> (23.3399, 55.5369)
  line L5 (21.0607, 60.4361) -> (21.7601, 59.6743)
  curve K15 (-21.4163, 59.0625) -> (-22.7131, 59.9644)
  line L6 (-34.4732, 58.6128) -> (-32.7992, 60.4361)
  curve K16 (-34.8613, 50.4161) -> (-34.4732, 58.6128)
  curve K17 (-34.4729, 47.5027) -> (-34.8613, 50.4161)
  curve K18 (-34.2161, 44.4991) -> (-34.4729, 47.5027)
  curve K19 (-34.0919, 41.4991) -> (-34.2161, 44.4991)
  curve K20 (-34.0692, 39.9991) -> (-34.0919, 41.4991)
  curve K21 (-34.0919, 38.4991) -> (-34.0692, 39.9991)
  curve K22 (-34.0919, 38.4991) -> (-34.2161, 35.4991)
  curve K23 (-34.4729, 32.4955) -> (-34.2161, 35.4991)
  line L7 (-23.7522, 38.4991) -> (-30.319, 38.4991)
  line L8 (-30.319, 35.4991) -> (-23.7522, 35.4991)
  line L9 (-23.7522, 44.4991) -> (-30.319, 44.4991)
  line L10 (-30.319, 41.4991) -> (-23.7522, 41.4991)
  line L11 (-26.3392, 50.4991) -> (-30.319, 50.4991)
  line L12 (-30.319, 47.4991) -> (-26.3392, 47.4991)
  line L13 (-2.454, 39.9991) -> (16.5436, 39.9991)
  line L14 (49, 49.9991) -> (7.5, 49.9991)
  line L15 (49, 29.9991) -> (7.5, 29.9991)
  line L16 (32.5785, 49.9991) -> (20.5106, 49.9991)
  line L17 (32.5785, 29.9991) -> (20.5106, 29.9991)
  line L18 (20.5106, 29.9991) -> (20.5106, 49.9991)
  curve K24 (-5.8693, 25.0204) -> (1.6863, 24.3869)
  curve K25 (-5.8693, 54.9778) -> (1.6863, 55.6114)
  curve K26 (-32.7992, 19.5622) -> (-25.5215, 18.3445)
  curve K27 (-22.7131, 20.0338) -> (-25.5215, 18.3445)
  curve K28 (-5.8693, 25.0204) -> (-13.4249, 24.3869)
  curve K29 (10.9746, 20.0338) -> (13.7829, 18.3445)
  curve K30 (13.7829, 18.3445) -> (21.0607, 19.5622)
  curve K31 (14.9178, 39.9991) -> (14.991, 38.4401)
  curve K32 (14.9178, 39.9991) -> (14.991, 41.5582)
  curve K33 (13.7829, 61.6537) -> (21.0607, 60.4361)
  curve K34 (10.9746, 59.9644) -> (13.7829, 61.6537)
  curve K35 (-5.8693, 54.9778) -> (-13.4249, 55.6114)
  curve K36 (-22.7131, 59.9644) -> (-25.5215, 61.6537)
  curve K37 (-32.7992, 60.4361) -> (-25.5215, 61.6537)
  curve K38 (-21.2077, 21.0728) -> (-21.4163, 20.9358)
  curve K39 (-13.5094, 24.37) -> (-21.2077, 21.0728)
  curve K40 (-13.4249, 24.3869) -> (-13.5094, 24.37)
  curve K41 (1.6863, 24.3869) -> (1.7709, 24.37)
  curve K42 (9.4692, 21.0728) -> (1.7709, 24.37)
  curve K43 (9.4692, 21.0728) -> (9.6778, 20.9358)
  curve K44 (9.6778, 20.9358) -> (10.9746, 20.0338)
  curve K45 (9.6778, 59.0625) -> (10.9746, 59.9644)
  curve K46 (9.4692, 58.9255) -> (9.6778, 59.0625)
  curve K47 (1.7709, 55.6283) -> (9.4692, 58.9255)
  curve K48 (1.6863, 55.6114) -> (1.7709, 55.6283)
  curve K49 (-13.4249, 55.6114) -> (-13.5094, 55.6283)
  curve K50 (-21.2077, 58.9255) -> (-13.5094, 55.6283)
  curve K51 (-21.2077, 58.9255) -> (-21.4163, 59.0625)
  arc A1 centre (4.1307, 49.9991) radius 2.5 clockwise from (5.0002, 47.6552) to (2.0117, 48.6726)
  arc A2 centre (4.1307, 29.9991) radius 2.5 clockwise from (2.0117, 31.3257) to (5.0002, 32.3431)
  arc A3 centre (-15.8693, 29.9991) radius 2.5 clockwise from (-15.9266, 32.4985) to (-13.7502, 31.3257)
  arc A4 centre (-15.8693, 49.9991) radius 2.5 clockwise from (-13.7502, 48.6726) to (-15.8119, 47.4998)
  arc A5 centre (-26.3392, 30.9991) radius 1.5 clockwise from (-26.3392, 32.4991) to (-26.3392, 29.4991)
  arc A6 centre (-30.319, 30.9991) radius 1.5 clockwise from (-30.319, 29.4991) to (-30.319, 32.4991)
  arc A7 centre (17.3404, 24.3819) radius 6 clockwise from (23.3399, 24.4614) to (21.7601, 20.324)
  arc A8 centre (17.3404, 55.6164) radius 6 clockwise from (21.7601, 59.6743) to (23.3399, 55.5369)
  arc A9 centre (-23.7522, 36.9991) radius 1.5 clockwise from (-23.7522, 38.4991) to (-23.7522, 35.4991)
  arc A10 centre (-30.319, 36.9991) radius 1.5 clockwise from (-30.319, 35.4991) to (-30.319, 38.4991)
  arc A11 centre (-30.319, 42.9991) radius 1.5 clockwise from (-30.319, 41.4991) to (-30.319, 44.4991)
  arc A12 centre (-23.7522, 42.9991) radius 1.5 clockwise from (-23.7522, 44.4991) to (-23.7522, 41.4991)
  arc A13 centre (-30.319, 48.9991) radius 1.5 clockwise from (-30.319, 47.4991) to (-30.319, 50.4991)
  arc A14 centre (-26.3392, 48.9991) radius 1.5 clockwise from (-26.3392, 50.4991) to (-26.3392, 47.4991)
  circle C1 centre (-29.8693, 56.4991) radius 2.55
  circle C2 centre (18.1307, 56.4991) radius 2.55
  circle C3 centre (-29.8693, 23.4991) radius 2.55
  circle C4 centre (18.1307, 23.4991) radius 2.55
  circle C5 centre (18.1307, 23.4991) radius 3.025
  circle C6 centre (18.1307, 56.4991) radius 3.025
  circle C7 centre (18.1307, 23.4991) radius 5.025
  circle C8 centre (18.1307, 56.4991) radius 5.025
  arc A15 centre (21.2571, 58.9913) radius 9.0231 clockwise from (20.5106, 49.9991) to (14.2014, 53.3668)
  arc A16 centre (21.2571, 21.0069) radius 9.0231 clockwise from (14.2014, 26.6314) to (20.5106, 29.9991)
  arc A17 centre (42.6327, 71.4187) radius 23.6619 clockwise from (32.5785, 49.9991) to (22.4227, 59.1125)
  arc A18 centre (42.6327, 8.5795) radius 23.6619 clockwise from (22.4227, 20.8857) to (32.5785, 29.9991)
  arc A19 centre (24.1325, 39.9991) radius 13.0895 clockwise from (32.5785, 49.9991) to (32.5785, 29.9991)
  circle C9 centre (-15.8693, 49.9991) radius 1.05
  circle C10 centre (4.1307, 49.9991) radius 1.05
  circle C11 centre (-15.8693, 29.9991) radius 1.05
  circle C12 centre (4.1307, 29.9991) radius 1.05
  point P77 (14.2014, 53.3668)
  point P83 (14.2014, 26.6314)
  point P78 (20.5106, 49.9991)
  point P84 (20.5106, 29.9991)
  point P85 (7.5, 49.9991)
  point P87 (7.5, 29.9991)
  point P86 (49, 49.9991)
  point P88 (49, 29.9991)
  point P89 (22.4227, 59.1125)
  point P93 (22.4227, 20.8857)
  point P90 (32.5785, 49.9991)
  point P94 (32.5785, 29.9991)
  point P95 (32.5785, 49.9991)
  point P96 (20.5106, 29.9991)
  point P97 (32.5785, 29.9991)
  concentric C4 C5
  concentric C2 C6
  concentric C4 C7
  concentric C6 C8
  equal C7 C8
  tangent C8 A15
  coincident C8 P77
  symmetric P77 L13 P83
  symmetric P78 L13 P84
  symmetric A15 L13 A16
  horizontal L14
  symmetric L13 P85 P87
  symmetric L13 P86 P88
  coincident P78 L14
  tangent C8 A17
  coincident C8 P89
  symmetric L13 P89 P93
  symmetric L13 P90 P94
  symmetric L13 A17 A18
  coincident L14 P95
  vertical P90 P95
  symmetric P78 L13 P96
  symmetric L13 P95 P97
  coincident L14 P90
  dimension "d713" diameter C5 = 6.05
  dimension "d714" diameter C6 = 6.05 (= "d713")
  dimension "d715" diameter C7 = 10.05 (= "d713 + 4 mm")
  dimension "d716" distance L13 L14 = 10
sketch "Sketch65" plane through (0, -46, 0) normal (0, -1, 0) x axis (1, 0, 0)
  circle C1 centre (-28.7111, 17.4065) radius 0.975
sketch "Sketch66" plane through (0, -34, 0) normal (0, 1, 0) x axis (-1, 0, 0)
  curve K1 (29.1562, 16.539) -> (27.8436, 17.8516)
  arc A1 centre (28.7111, 17.4065) radius 0.975 clockwise from (29.1562, 16.539) to (27.8436, 17.8516)
work_axis "WorkAxis7"
position "Position2"
work_plane "WorkPlane12" AlongDistance 10.5
sketch "motor diams" plane through (0, 0, 5) normal (0, 0, 1) x axis (-1, 0, 0)
  line L1 (45.6984, 88.6696) -> (46.2975, 88.6508)
  line L2 (46.3634, 90.7497) -> (45.7643, 90.7686)
  line L3 (53.0046, 94.732) -> (53.0363, 95.3296)
  line L4 (50.9392, 95.441) -> (50.9075, 94.8433)
  line L5 (57.0019, 88.0092) -> (57.5891, 87.9367)
  line L6 (57.8463, 90.0209) -> (57.259, 90.0934)
  line L7 (42.6895, 76.3401) -> (26.9801, 60.9632)
  curve K1 (42.6895, 76.3401) -> (58.4159, 84.3161)
  curve K2 (52.3801, 102.7764) -> (47.6742, 96.5557)
  curve K3 (43.0511, 92.8338) -> (39.5769, 81.6893)
  line L8 (25.1132, 67.5318) -> (39.5769, 81.6893)
  curve K4 (25.1132, 67.5318) -> (14.076, 61.8127)
  curve K5 (10.9746, 59.9644) -> (9.6778, 59.0625)
  curve K6 (9.6778, 59.0625) -> (7.6307, 54.6035)
  line L9 (7.6307, 45.4991) -> (7.6307, 54.6035)
  curve K7 (10.6307, 45.4991) -> (22.3176, 52.2655)
  curve K8 (22.3176, 52.2655) -> (26.9801, 60.9632)
  curve K9 (65.0703, 88.0717) -> (52.3801, 102.7764)
  curve K10 (47.6742, 96.5557) -> (43.0511, 92.8338)
  curve K11 (58.4159, 84.3161) -> (65.0703, 88.0717)
  curve K12 (14.076, 61.8127) -> (10.9746, 59.9644)
  arc A1 centre (46.3305, 89.7003) radius 1.05 clockwise from (46.3634, 90.7497) to (46.2975, 88.6508)
  arc A2 centre (45.7313, 89.7191) radius 1.05 clockwise from (45.6984, 88.6696) to (45.7643, 90.7686)
  circle C1 centre (18.1307, 56.4991) radius 1.55
  arc A3 centre (51.956, 94.7877) radius 1.05 clockwise from (53.0046, 94.732) to (50.9075, 94.8433)
  arc A4 centre (51.9878, 95.3853) radius 1.05 clockwise from (50.9392, 95.441) to (53.0363, 95.3296)
  circle C2 centre (51.7305, 89.3877) radius 2.7
  arc A5 centre (57.1305, 89.0513) radius 1.05 clockwise from (57.0019, 88.0092) to (57.259, 90.0934)
  arc A6 centre (57.7177, 88.9788) radius 1.05 clockwise from (57.8463, 90.0209) to (57.5891, 87.9367)
  arc A7 centre (9.1307, 45.4991) radius 1.5 clockwise from (10.6307, 45.4991) to (7.6307, 45.4991)
  circle C3 centre (51.7305, -9.3895) radius 2.7
  circle C4 centre (-63.469, -9.3895) radius 2.7
  circle C5 centre (-63.469, 89.3877) radius 2.7
  circle C6 centre (51.7305, -9.3895) radius 38.1
  circle C7 centre (51.7305, 89.3877) radius 38.1
  circle C8 centre (-63.469, -9.3895) radius 38.1
  circle C9 centre (-63.469, 89.3877) radius 38.1
  concentric C3 C6
  concentric C2 C7
  concentric C4 C8
  concentric C5 C9
  dimension "d802" diameter C6 = 76.2 (= "3")
  dimension "d803" diameter C7 = 76.2 (= "3")
  dimension "d804" diameter C8 = 76.2 (= "3")
  dimension "d805" diameter C9 = 76.2 (= "3")
sketch "Sketch67" plane through (0, 0, 17.5) normal (0, 0, 1) x axis (1, 0, 0)
  line L1 (-32.5785, -49.9991) -> (-20.5106, -49.9991)
  line L2 (-32.5785, -29.9991) -> (-20.5106, -29.9991)
  line L3 (-20.5106, -29.9991) -> (-20.5106, -28.2837)
  line L4 (-44.8223, -29.9991) -> (-32.5785, -29.9991)
  line L5 (-44.8223, -49.9991) -> (-44.8223, -29.9991)
  line L6 (-32.5785, -49.9991) -> (-44.8223, -49.9991)
  line L7 (2.454, -39.9991) -> (-16.5436, -39.9991)
  line L8 (-20.5106, -49.9991) -> (-20.5106, -51.7145)
  line L9 (-28.8223, -49.9991) -> (-28.8223, -29.9991)
  point P4 (-20.5106, -29.9991)
  point P7 (-20.5106, -29.9991)
  point P5 (-32.5785, -29.9991)
  point P8 (-32.5785, -29.9991)
  point P3 (-32.5785, -49.9991)
  point P11 (-32.5785, -49.9991)
  point P6 (-20.5106, -28.2837)
  point P14 (-20.5106, -51.7145)
  point P15 (-20.5106, -49.9991)
  point P16 (-28.8223, -29.9991)
  point P17 (-28.8223, -49.9991)
  coincident P4 P7
  perpendicular L2 L3
  coincident P5 P8
  parallel L2 L4
  perpendicular L4 L5
  coincident P3 P11
  symmetric P6 L7 P14
  symmetric P7 L7 P15
  coincident L2 P16
  coincident L1 P17
  perpendicular L1 L9
  parallel L4 L6
  dimension "d844" distance L5 L9 = 16
revolve "Revolve1" sketch "Sketch67" AlongAngle 90 AgainstAngle 90
sketch "Sketch75" plane through (0, -49.9991, 0) normal (0, -1, 0) x axis (1, 0, 0)
  line L1 (-28.8223, 29.4065) -> (-28.8223, 17.4065)
  line L2 (-28.8223, 1.4065) -> (-28.8223, 17.4065)
  line L3 (-28.8223, 33.5) -> (-28.8223, 21.2561)
  line L4 (-28.8223, 17.5) -> (-28.8223, 13.7439)
  arc A1 centre (-28.8223, 17.5) radius 16 clockwise from (-28.8223, 1.5) to (-28.8223, 33.5)
  arc A2 centre (-23.7386, 15.4065) radius 14.8944 clockwise from (-28.8223, 1.4065) to (-28.8223, 29.4065)
  point P6 (-28.8223, 17.4065)
  point P8 (-28.8223, 17.4065)
  point P5 (-28.7111, 17.4065)
  point P7 (-28.8223, 29.4065)
  point P9 (-28.8223, 1.4065)
  coincident P6 P8
  horizontal P5 P8
  dimension "d808" distance P6 P7 = 12
  dimension "d809" distance P8 P9 = 16
sketch "Sketch76" plane through (0, -29.9991, 0) normal (0, 1, 0) x axis (-1, 0, 0)
  line L1 (28.8223, 1.5) -> (28.8223, 33.5)
  line L2 (28.8223, 29.4065) -> (28.8223, 17.4065)
  line L3 (28.8223, 1.4065) -> (28.8223, 17.4065)
  arc A1 centre (28.8223, 17.5) radius 16 clockwise from (28.8223, 33.5) to (28.8223, 1.5)
  arc A2 centre (23.7386, 15.4065) radius 14.8944 clockwise from (28.8223, 29.4065) to (28.8223, 1.4065)
extrude "Extrude101" add sketch "Sketch75" profile of L1 L2 A2 along normal blind 2
extrude "Extrude102" add sketch "Sketch76" along normal blind 2
extrude "Extrude89" add sketch "cam-mount-base" profile of L4 A7 K11 K12 K13 K14 A8 L5 K28 C5 C6 C7 C8 A15 A16 A17 A18 L16 L17 along normal blind 25
extrude "Extrude93" add sketch "cam-mount-base" profile of L4 A7 K11 K12 K13 K14 A8 L5 K28 C5 C6 C7 C8 A15 A16 A17 A18 L16 L17 against normal blind 7
sketch "Sketch80" plane through (0, -49.9991, 0) normal (0, 1, 0) x axis (-1, 0, 0)
  line L1 (28.8223, 32) -> (28.8223, 1.5)
  line L2 (20.5106, 32) -> (28.8223, 32)
  line L3 (20.5106, 0) -> (20.5106, 32)
  line L4 (32.5785, 0) -> (20.5106, 0)
  line L5 (32.5785, 1.9471) -> (32.5785, 0)
  line L6 (13.1, 0) -> (32.5785, 0)
  line L7 (13.1, 2.5) -> (13.1, 0)
  line L8 (32.5785, 2.5) -> (13.1, 2.5)
  line L9 (32.5785, 0) -> (32.5785, 2.5)
  arc A1 centre (28.8223, 17.5) radius 16 clockwise from (32.5785, 1.9471) to (28.8223, 1.5)
  point P8 (32.5785, 0)
  point P9 (32.5785, 0)
  horizontal L6
  vertical L7
  horizontal L8
  vertical L9
  coincident P8 P9
extrude "Extrude106" add sketch "Sketch80" profile of A1 L1 L3 L4 L5 L6 L8 L9 along normal blind 20
sketch "Sketch68" plane through (5.8693, -30.0098, 0) normal (1, 0, 0) x axis (0, 1, 0)
  line L1 (-37, 7) -> (21, 7)
  line L2 (-37, -10) -> (-37, 7)
  line L3 (21, -10) -> (-37, -10)
  line L4 (21, 7) -> (21, -10)
  line L5 (-37, 5) -> (21, 5)
  line L6 (17, 47) -> (-34, 47)
  line L7 (17, 32) -> (17, 47)
  line L8 (-34, 32) -> (17, 32)
  line L9 (-34, 47) -> (-34, 32)
  line L10 (-2.1, 21) -> (-17.9, 21)
  line L11 (-2.1, 44.5) -> (-2.1, 21)
  line L12 (-17.9, 44.5) -> (-2.1, 44.5)
  line L13 (-17.9, 21) -> (-17.9, 44.5)
  line L14 (-37, 0) -> (21, 0)
  circle C1 centre (-10, 21) radius 7.9
  point P6 (21, 5)
  point P7 (-37, 5)
  point P13 (-17.9, 21)
  point P14 (-2.1, 21)
  point P17 (21, 0)
  horizontal L1
  vertical L2
  horizontal L3
  vertical L4
  coincident L4 P6
  coincident L2 P7
  perpendicular L2 L5
  horizontal L6
  vertical L7
  horizontal L8
  vertical L9
  horizontal L10
  vertical L11
  horizontal L12
  vertical L13
  coincident C1 P13
  coincident C1 P14
  coincident L4 P17
  perpendicular L4 L14
  dimension "d745" diameter C1 = 15.8
  dimension "d778" distance L1 L14 = 7
shell "Shell2" innerThickness 2
extrude "Extrude91" cut sketch "Sketch68" profile of L8 C1 L10 L11 L12 L13 against normal blind 87
fillet "Fillet53" radius 2
fillet "Fillet66" radius 3
fillet "Fillet68" radius 2
extrude "Extrude95" cut of existing geometry blind -7
extrude "Extrude107" cut of existing geometry blind 39
extrude "Extrude108" cut of existing geometry blind -30
extrude "Extrude96" cut of existing geometry blind -7
sketch "Sketch78" plane through (0, -51.9991, 0) normal (0, -1, 0) x axis (1, 0, 0)
  line L1 (-29.1136, 27.1272) -> (-29.1136, 3.6857)
  arc A1 centre (-23.7386, 15.4065) radius 12.8944 clockwise from (-29.1136, 3.6857) to (-29.1136, 27.1272)
  circle C1 centre (-28.7111, 17.4065) radius 0.975
  circle C2 centre (-28.7111, 17.4065) radius 2
  concentric C1 C2
  dimension "d835" diameter C2 = 4
sketch "Sketch79" plane through (0, -27.9991, 0) normal (0, 1, 0) x axis (-1, 0, 0)
  curve K1 (29.1562, 16.539) -> (27.8436, 17.8516)
  line L1 (29.1136, 3.6857) -> (29.1136, 27.1272)
  arc A1 centre (23.7386, 15.4065) radius 12.8944 clockwise from (29.1136, 27.1272) to (29.1136, 3.6857)
  arc A2 centre (28.7111, 17.4065) radius 0.975 clockwise from (29.1562, 16.539) to (27.8436, 17.8516)
  circle C1 centre (28.7111, 17.4065) radius 2
  point P10 (28.7111, 17.4065)
  point P11 (28.7111, 17.4065)
  coincident P10 P11
  dimension "d834" diameter C1 = 4
extrude "Extrude97" cut sketch "Sketch65" along normal blind 11.5
extrude "Extrude104" cut sketch "Sketch78" profile of C1 C2 along normal blind 3.5
extrude "Extrude98" cut sketch "Sketch66" along normal blind 8.5
extrude "Extrude105" cut sketch "Sketch79" profile of K1 A2 C1 along normal blind 9
fillet "Fillet75" radius 0.5
fillet "Fillet76" radius 2
fillet "Fillet77" radius 1
fillet "Fillet78" radius 1
fillet "Fillet79" radius 3
fillet "Fillet80" radius 1
extrude "Extrude109" cut of existing geometry blind -3
extrude "Extrude110" cut of existing geometry blind -2
fillet "Fillet81" radius 3
fillet "Fillet82" radius 1.5
fillet "Fillet83" radius 1
fillet "Fillet84" radius 1
fillet "Fillet85" radius 1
